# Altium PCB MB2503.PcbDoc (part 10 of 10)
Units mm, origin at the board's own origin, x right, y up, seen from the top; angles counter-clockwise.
Board outline 127 x 97 mm, 6 copper layers (Top Layer, Signal Layer 1, Signal Layer 2, Signal Layer 3, Signal Layer 4, Bottom Layer), stack 1.557 mm thick; 572 components, 468 nets, 2377 pads, 1704 vias.
Unrouted connection lines stored in the file: 3.
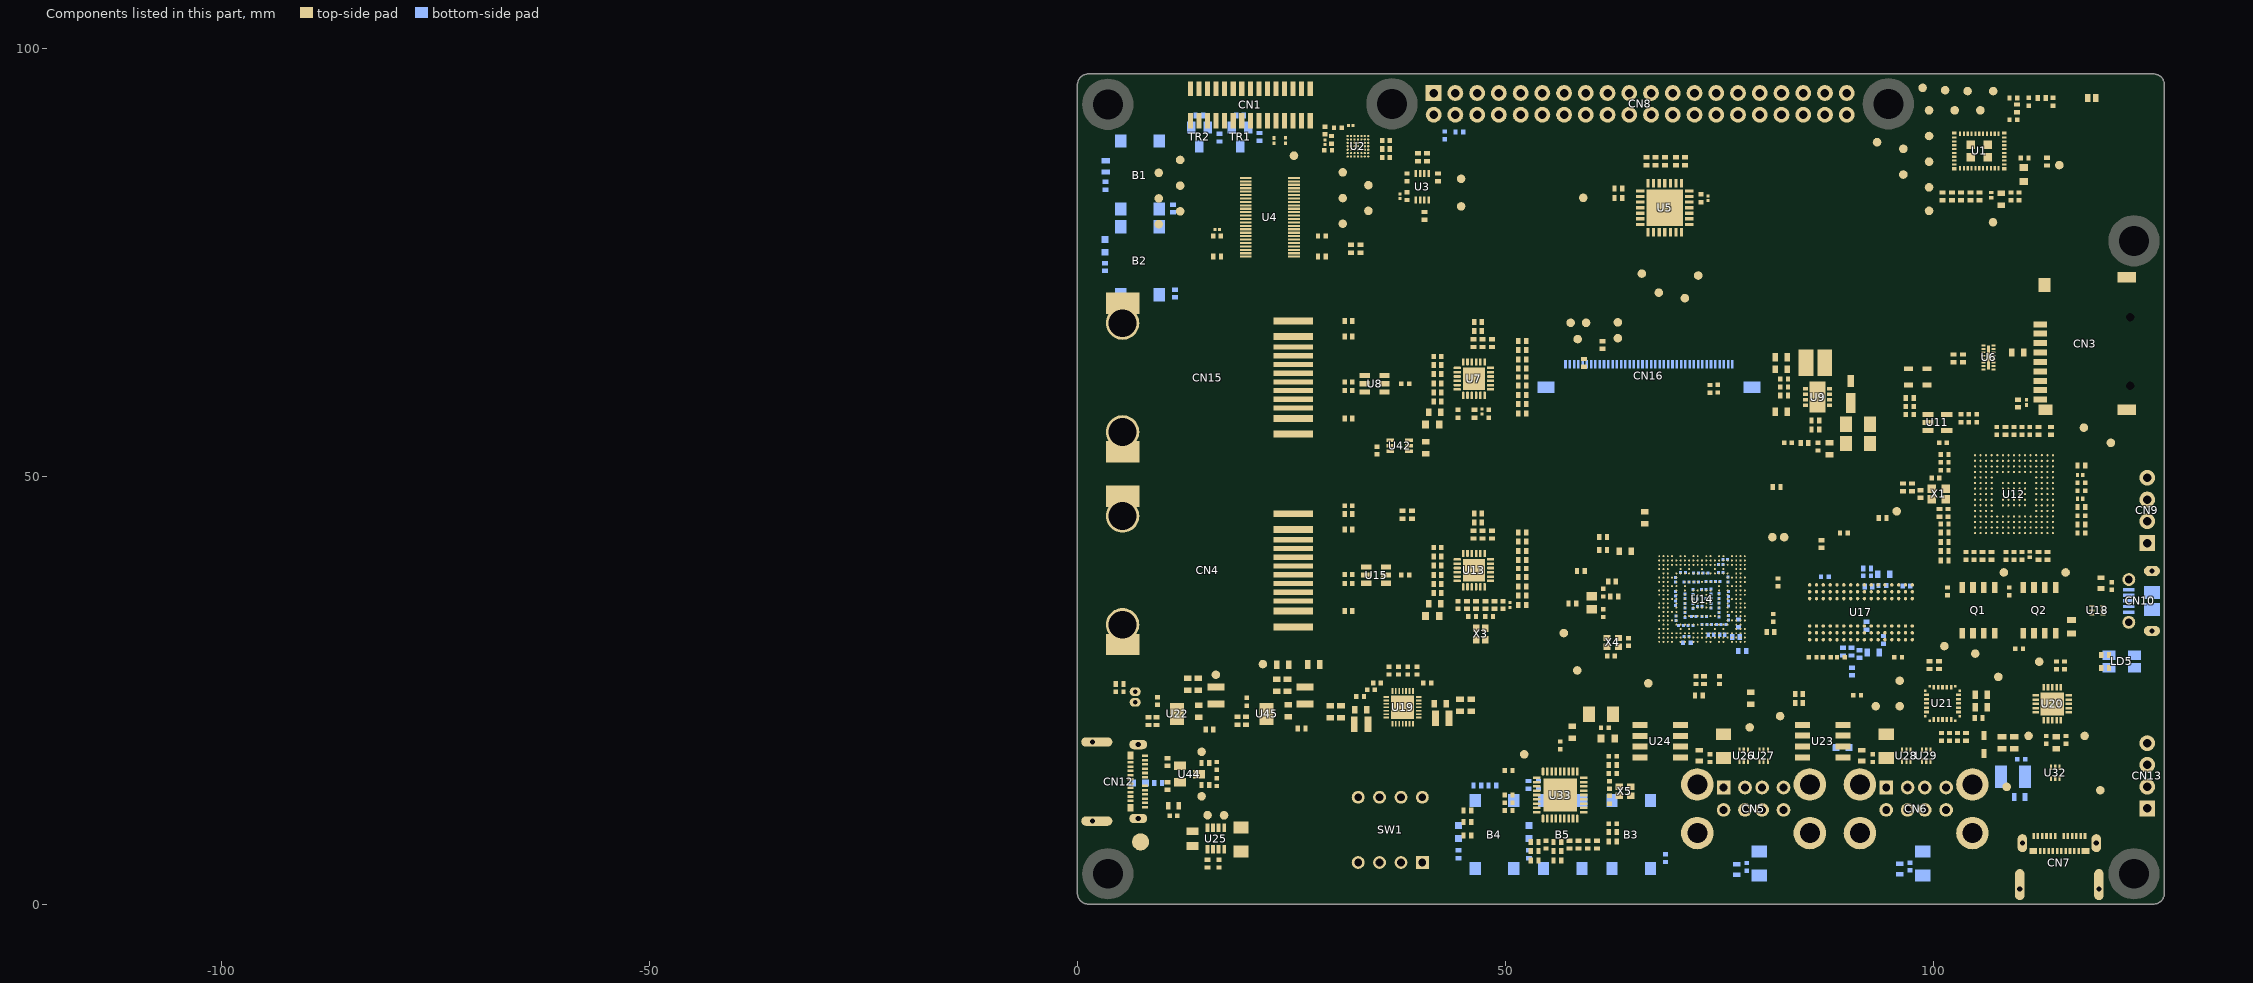
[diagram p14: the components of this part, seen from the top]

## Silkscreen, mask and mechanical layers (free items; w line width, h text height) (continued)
Drill Drawing:
  drawing of 528 lines, arcs and shapes, not listed
  text "MINIMUN PARAMETERS" at 152.3,145.65 h3
  text "PCB SPECIFICATIONS :" at 0.575,144.95 h3
  text "A.   MATERIAL :" at 0.575,140.95 h3
  text "FR-4" at 39.075,140.95 h3
  text "TG-170" at 55.575,140.95 h3
  text "X  TG-150" at 73.825,140.95 h3
  text "TG-140" at 89.825,140.95 h3
  text "DEFAULT" at 152.3,140.15 h3
  text "B.   MATERIAL FAMILY :" at 0.575,137.95 h3
  text "N/A" at 39.075,137.95 h3
  text "C.   SOLDERMASK COLOR :" at 0.575,134.95 h3
  text "GREEN" at 39.075,134.95 h3
  text "X  BLUE" at 55.575,134.95 h3
  text "RED" at 73.825,134.95 h3
  text "BLACK" at 89.825,134.95 h3
  text "TRACKS : 0.100mm           / GAPS : 0.100mm" at 152.3,134.4 h3
  text "D.   SILKSCREEN COLOR :" at 0.575,131.95 h3
  text "X  WHITE" at 39.075,131.95 h3
  text "YELLOW" at 55.575,131.95 h3
  text "BLACK" at 73.825,131.95 h3
  text "E.   SURFACE FINISH :" at 0.575,128.95 h3
  text "X  ENIG" at 39.075,128.95 h3
  text "IMMERSION SILVER" at 55.575,128.95 h3
  text "IMMERSION TIN" at 89.825,128.95 h3
  text "UNDER MPU" at 152.3,127.9 h3
  text "HASL" at 39.075,125.95 h3
  text "HASL (PB-FREE)" at 55.575,125.95 h3
  text "GOLDEN FINGER" at 89.825,125.95 h3
  text "F.   IMPEDANCE CONTROL :" at 0.575,122.95 h3
  text "NO" at 39.075,122.95 h3
  text "X  YES  (SEE IMPEDANCE TABLE FOR DETAIL INFORMATION)" at 55.575,122.95 h3
  text "TRACKS : 0.090mm           / GAPS : 0.080mm" at 152.3,122.15 h3
  text "G.   THROUGH VIA :" at 0.575,119.95 h3
  text "PLUG THE VIAS WHICH ARE COVERED WITH SOLDERMASK ONE OR TWO SIDE." at 39.075,119.95 h3
  text "PLUG MATERIAL :" at 39.075,116.95 h3
  text "X  SOLDERMASK" at 64.575,116.95 h3
  text "NON-CONDUCTIVE EPOXY." at 89.825,116.95 h3
  text "UNDER DDR" at 152.3,115.9 h3
  text "H.   STACK-UP :" at 0.575,113.95 h3
  text "SEE LAYER STACK-UP SEQUENCE FOR OVERALL THICKNESS." at 39.075,113.95 h3
  text "TRACKS : 0.090mm           / GAPS : 0.080mm" at 152.3,110.15 h3
  text "Layer" at 137.6,103.625 h2
  text "Name" at 145.967,103.625 h2
  text "Material" at 162.141,103.625 h2
  text "Thickness" at 176.675,103.625 h2
  text "Constant" at 188.615,103.625 h2
  text "Board Layer Stack" at 199.667,103.625 h2
  text "Top Overlay" at 145.967,99.625 h2
  text "Top Solder" at 145.967,95.625 h2
  text "Solder Resist" at 162.141,95.625 h2
  text "0,025mm" at 176.675,95.625 h2
  text "3.5" at 188.615,95.625 h2
  text "1" at 137.6,91.625 h2
  text "Top Layer" at 145.967,91.625 h2
  text "0,027mm" at 176.675,91.625 h2
  text "Dielectric 1" at 145.967,87.625 h2
  text "0,068mm" at 176.675,87.625 h2
  text "4" at 188.615,87.625 h2
  text "2" at 137.599,83.625 h2
  text "Signal Layer 1" at 145.967,83.625 h2
  text "0,033mm" at 176.675,83.625 h2
  text "Dielectric 2" at 145.967,79.625 h2
  text "0,510mm" at 176.675,79.625 h2
  text "4" at 188.615,79.625 h2
  text "3" at 137.6,75.625 h2
  text "Signal Layer 2" at 145.967,75.625 h2
  text "0,033mm" at 176.675,75.625 h2
  text "Dielectric 3" at 145.967,71.625 h2
  text "0,215mm" at 176.675,71.625 h2
  text "5" at 188.615,71.625 h2
  text "4" at 137.6,67.625 h2
  text "Signal Layer 3" at 145.967,67.625 h2
  text "0,033mm" at 176.675,67.625 h2
  text "Dielectric 4" at 145.967,63.625 h2
  text "0,510mm" at 176.675,63.625 h2
  text "4" at 188.615,63.625 h2
  text "5" at 137.6,59.625 h2
  text "Signal Layer 4" at 145.967,59.625 h2
  text "0,033mm" at 176.675,59.625 h2
  text "Dielectric5" at 145.967,55.625 h2
  text "0,068mm" at 176.675,55.625 h2
  text "4" at 188.615,55.625 h2
  text "6" at 137.6,51.625 h2
  text "Bottom Layer" at 145.967,51.625 h2
  text "0,027mm" at 176.675,51.625 h2
  text "Bottom Solder" at 145.967,47.625 h2
  text "Solder Resist" at 162.141,47.625 h2
  text "0,025mm" at 176.675,47.625 h2
  text "3.5" at 188.615,47.625 h2
  text "Bottom Overlay" at 145.967,43.625 h2
  text "Symbol" at 138.018,31.777 h2.4
  text "Count" at 147.415,31.777 h2.4
  text "Hole Size" at 158.026,31.777 h2.4
  text "Plated" at 177.26,31.777 h2.4
  text "Hole Type" at 185.512,31.777 h2.4
  text "Drill Layer Pair" at 197.522,31.777 h2.4
  text "Via/Pad" at 220.701,31.777 h2.4
  text "Pad Shape" at 230.543,31.777 h2.4
  text "Template" at 243.403,31.777 h2.4
  text "Hole Tolerance (+)" at 271.234,31.777 h2.4
  text "Hole Tolerance (-)" at 291.312,31.777 h2.4
  text "29" at 147.415,27.637 h2
  text "0.100mm (3.94mil)" at 158.026,27.637 h2
  text "PTH" at 177.26,27.637 h2
  text "Round" at 185.512,27.637 h2
  text "Top Layer - Signal Layer 1" at 197.522,27.637 h2
  text "Via" at 220.701,27.637 h2
  text "Rounded" at 230.543,27.637 h2
  text "v26h10m0" at 243.403,27.637 h2
  text "322" at 147.415,23.497 h2
  text "0.200mm (7.87mil)" at 158.026,23.497 h2
  text "PTH" at 177.26,23.497 h2
  text "Round" at 185.512,23.497 h2
  text "Top Layer - Bottom Layer" at 197.522,23.497 h2
  text "Via" at 220.701,23.497 h2
  text "Rounded" at 230.543,23.497 h2
  text "(Mixed)" at 243.403,23.497 h2
  text "1353" at 147.415,19.357 h2
  text "0.250mm (9.84mil)" at 158.026,19.357 h2
  text "PTH" at 177.26,19.357 h2
  text "Round" at 185.512,19.357 h2
  text "Top Layer - Bottom Layer" at 197.522,19.357 h2
  text "Via" at 220.701,19.357 h2
  text "Rounded" at 230.543,19.357 h2
  text "(Mixed)" at 243.403,19.357 h2
  text "2" at 147.415,15.218 h2
  text "0.500mm (19.69mil)" at 158.026,15.218 h2
  text "PTH" at 177.26,15.218 h2
  text "Round" at 185.512,15.218 h2
  text "Top Layer - Bottom Layer" at 197.522,15.218 h2
  text "Pad" at 220.701,15.218 h2
  text "Rounded" at 230.543,15.218 h2
  text "(Mixed)" at 243.403,15.218 h2
  text "0.050mm (1.97mil)" at 271.234,15.218 h2
  text "0.050mm (1.97mil)" at 291.312,15.218 h2
  text "2" at 147.415,11.078 h2
  text "0.600mm (23.62mil)" at 158.026,11.078 h2
  text "PTH" at 177.26,11.078 h2
  text "Slot" at 185.512,11.078 h2
  text "Top Layer - Bottom Layer" at 197.522,11.078 h2
  text "Pad" at 220.701,11.078 h2
  text "Rounded" at 230.543,11.078 h2
  text "r190_120h60_130r60m200_130" at 243.403,11.078 h2
  text "4" at 147.415,6.938 h2
  text "0.600mm (23.62mil)" at 158.026,6.938 h2
  text "PTH" at 177.26,6.938 h2
  text "Slot" at 185.512,6.938 h2
  text "Top Layer - Bottom Layer" at 197.522,6.938 h2
  text "Pad" at 220.701,6.938 h2
  text "Rounded" at 230.543,6.938 h2
  text "r210_110h60_160r55m220_120" at 243.403,6.938 h2
  text "4" at 147.415,2.799 h2
  text "0.600mm (23.62mil)" at 158.026,2.799 h2
  text "PTH" at 177.26,2.799 h2
  text "Slot" at 185.512,2.799 h2
  text "Top Layer - Bottom Layer" at 197.522,2.799 h2
  text "Pad" at 220.701,2.799 h2
  text "Rounded" at 230.543,2.799 h2
  text "r260_110h60_210r55m270_120" at 243.403,2.799 h2
  text "10" at 147.415,-1.341 h2
  text "0.900mm (35.43mil)" at 158.026,-1.341 h2
  text "PTH" at 177.26,-1.341 h2
  text "Round" at 185.512,-1.341 h2
  text "Top Layer - Bottom Layer" at 197.522,-1.341 h2
  text "Pad" at 220.701,-1.341 h2
  text "(Mixed)" at 230.543,-1.341 h2
  text "(Mixed)" at 243.403,-1.341 h2
  text "16" at 147.415,-5.481 h2
  text "0.920mm (36.22mil)" at 158.026,-5.481 h2
  text "PTH" at 177.26,-5.481 h2
  text "Round" at 185.512,-5.481 h2
  text "Top Layer - Bottom Layer" at 197.522,-5.481 h2
  text "Pad" at 220.701,-5.481 h2
  text "(Mixed)" at 230.543,-5.481 h2
  text "(Mixed)" at 243.403,-5.481 h2
  text "2" at 147.415,-9.621 h2
  text "1.000mm (39.37mil)" at 158.026,-9.621 h2
  text "NPTH" at 177.26,-9.621 h2
  text "Round" at 185.512,-9.621 h2
  text "Top Layer - Bottom Layer" at 197.522,-9.621 h2
  text "Pad" at 220.701,-9.621 h2
  text "Rounded" at 230.543,-9.621 h2
  text "c50hn100m110p0" at 243.403,-9.621 h2
  text "48" at 147.415,-13.76 h2
  text "1.000mm (39.37mil)" at 158.026,-13.76 h2
  text "PTH" at 177.26,-13.76 h2
  text "Round" at 185.512,-13.76 h2
  text "Top Layer - Bottom Layer" at 197.522,-13.76 h2
  text "Pad" at 220.701,-13.76 h2
  text "Rounded" at 230.543,-13.76 h2
  text "(Mixed)" at 243.403,-13.76 h2
  text "8" at 147.415,-17.9 h2
  text "2.330mm (91.73mil)" at 158.026,-17.9 h2
  text "PTH" at 177.26,-17.9 h2
  text "Round" at 185.512,-17.9 h2
  text "Top Layer - Bottom Layer" at 197.522,-17.9 h2
  text "Pad" at 220.701,-17.9 h2
  text "Rounded" at 230.543,-17.9 h2
  text "c380h233" at 243.403,-17.9 h2
  text "4" at 147.415,-22.04 h2
  text "3.250mm (127.95mil)" at 158.026,-22.04 h2
  text "PTH" at 177.26,-22.04 h2
  text "Round" at 185.512,-22.04 h2
  text "Top Layer - Bottom Layer" at 197.522,-22.04 h2
  text "Pad" at 220.701,-22.04 h2
  text "Rounded" at 230.543,-22.04 h2
  text "c390h325m400" at 243.403,-22.04 h2
  text "6" at 147.415,-26.179 h2
  text "3.500mm (137.79mil)" at 158.026,-26.179 h2
  text "PTH" at 177.26,-26.179 h2
  text "Round" at 185.512,-26.179 h2
  text "Top Layer - Bottom Layer" at 197.522,-26.179 h2
  text "Pad" at 220.701,-26.179 h2
  text "Rounded" at 230.543,-26.179 h2
  text "c600h350" at 243.403,-26.179 h2
  text "1810 Total" at 147.415,-30.319 h2
  text "Slot definitions :" at 138.018,-33.217 h2
  text "Routed Path Length" at 151.64,-33.217 h2
  text "= Calculated from tool start centre position to tool end centre position." at 168.523,-33.217 h2
  text "Hole Length" at 151.64,-34.873 h2
  text "= Routed Path Length + Tool Size = Slot length as defined in the PCB layout" at 162.256,-34.873 h2

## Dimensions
127,95.73 to 0,95.73 on M2-Board Dimensions
33.15,96.75 to 98.15,97.025 on M8-Bottom Info
1.27,0 to 1.27,97 on M2-Board Dimensions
